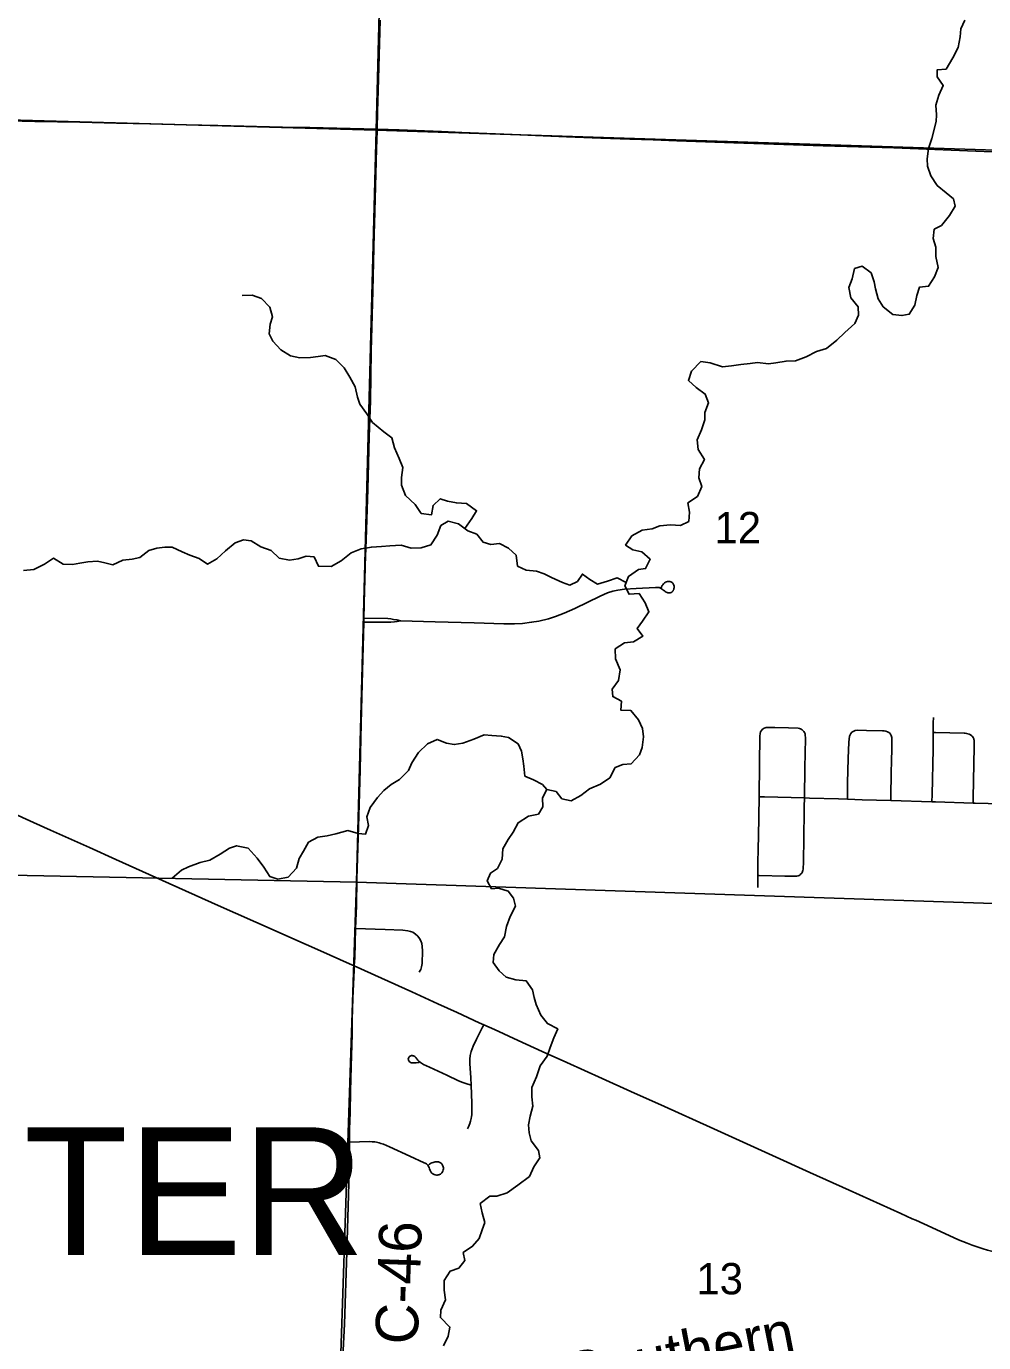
# Model space of a CAD drawing. Extents: x 0 to 34, y 0 to 22.
# Drawn here: x 4.336 to 5.615, y 17.97 to 19.729 of the extents above; entities that cross this region are included whole.
import ezdxf

# ---------------------------------------------------------------- set-up
doc = ezdxf.new("R2010")
doc.units = 0
for name, color, linetype in [('GM_X_Corporation', 7, 'Continuous'), ('GM_X_County_Road', 7, 'Continuous'), ('GM_X_County_Road_Text', 7, 'Continuous'), ('GM_X_Minor_River', 7, 'Continuous'), ('GM_X_Rail_Line_Text', 7, 'Continuous'), ('GM_X_Section_Text', 7, 'Continuous'), ('GM_X_State_Route', 7, 'Continuous'), ('GM_X_Township_Road', 7, 'Continuous'), ('GM_X_Township_Text', 7, 'Continuous')]:
    doc.layers.add(name, color=color, linetype=linetype)

msp = doc.modelspace()

# ---------------------------------------------------------------- linework, layer by layer
at = {"layer": 'GM_X_Corporation'}
for points in [[(3.7914, 20.5987), (3.8107, 20.5986), (4.8123, 20.5837), (4.829, 20.5833), (4.8036, 19.5906), (3.7742, 19.6197)], [(4.829, 20.5833), (5.8164, 20.5638), (5.7981, 19.5979), (5.7974, 19.5584), (4.8036, 19.5906)], [(3.7742, 19.6197), (4.8036, 19.5906), (4.7775, 18.5857), (3.7435, 18.6067)], [(4.8036, 19.5906), (5.7974, 19.5584), (5.7756, 18.586), (5.7749, 18.5522), (4.7775, 18.5857)], [(3.7435, 18.6067), (4.7775, 18.5857), (4.7439, 17.5807), (3.7219, 17.5988)], [(4.7775, 18.5857), (5.7749, 18.5522), (5.7585, 17.5867), (5.7581, 17.5537), (4.7439, 17.5807)]]:
    msp.add_lwpolyline(points, close=True, dxfattribs=at)
at = {"layer": 'GM_X_County_Road'}
for points in [[(4.8051, 19.5918), (4.8056, 19.6152), (4.8065, 19.6437), (4.8092, 19.7375)], [(4.8016, 19.4655), (4.8044, 19.5655), (4.8051, 19.5898), (4.8051, 19.5918)], [(4.7886, 18.9874), (4.7891, 19.0092), (4.7905, 19.0433), (4.7926, 19.111), (4.7936, 19.1452), (4.7946, 19.1809), (4.796, 19.2289), (4.7971, 19.2953), (4.7993, 19.3761), (4.8013, 19.4525), (4.8016, 19.4655)], [(4.7871, 18.9333), (4.7872, 18.9384), (4.7877, 18.9564), (4.7883, 18.9775), (4.7886, 18.9874)], [(4.7763, 18.5237), (4.7773, 18.5541), (4.778, 18.5901), (4.7796, 18.6453), (4.7804, 18.6745), (4.7823, 18.736), (4.7834, 18.7782), (4.7843, 18.8161), (4.7855, 18.8676), (4.7871, 18.9333)], [(5.548, 18.7858), (5.5482, 18.7985), (5.5483, 18.8059)], [(5.3153, 18.7), (5.316, 18.7437), (5.3164, 18.7809), (5.3169, 18.7844), (5.3175, 18.7866), (5.3185, 18.7884), (5.3196, 18.7898)], [(5.3759, 18.6984), (5.3767, 18.7392), (5.377, 18.7578), (5.3774, 18.7783), (5.3771, 18.7825), (5.3768, 18.7841), (5.3763, 18.7856), (5.3754, 18.7872), (5.3745, 18.7882), (5.3731, 18.7895), (5.3717, 18.7904), (5.3706, 18.7908), (5.3694, 18.7912), (5.3678, 18.7915), (5.3545, 18.792), (5.3364, 18.7926), (5.3248, 18.7925), (5.3236, 18.7922), (5.3221, 18.7915), (5.3207, 18.7907), (5.3196, 18.7898)], [(5.4335, 18.6966), (5.4336, 18.7009), (5.4337, 18.7187), (5.4345, 18.751), (5.4355, 18.7727), (5.4364, 18.7808), (5.437, 18.7828), (5.438, 18.7846), (5.4394, 18.7861), (5.4411, 18.7873), (5.4436, 18.7884), (5.4468, 18.7889), (5.4587, 18.7886), (5.4804, 18.7879), (5.4827, 18.7878), (5.4848, 18.7874), (5.4868, 18.7868), (5.488, 18.7863), (5.4895, 18.7852), (5.491, 18.7837), (5.4919, 18.7818), (5.4926, 18.7792), (5.4927, 18.7764), (5.4928, 18.7735), (5.4926, 18.7604), (5.4924, 18.7511), (5.4921, 18.7287), (5.4916, 18.7032), (5.4915, 18.7001), (5.4915, 18.6948)], [(5.5464, 18.6931), (5.5465, 18.7028), (5.5478, 18.7636), (5.548, 18.7858)], [(5.6014, 18.6915), (5.6016, 18.6985), (5.6024, 18.7437), (5.6027, 18.7666), (5.6026, 18.7753), (5.6025, 18.7764), (5.6023, 18.7774), (5.6019, 18.7783), (5.6014, 18.7792), (5.6006, 18.7802), (5.5997, 18.7813), (5.5979, 18.7826), (5.596, 18.7835), (5.5942, 18.7842), (5.5926, 18.7845), (5.5906, 18.7847), (5.5892, 18.7848), (5.5511, 18.7857), (5.548, 18.7858)], [(5.3138, 18.5947), (5.3138, 18.6107), (5.3142, 18.6312), (5.3144, 18.6467), (5.3153, 18.7)], [(5.3138, 18.5947), (5.3154, 18.5947), (5.3499, 18.594), (5.364, 18.5937), (5.366, 18.5939), (5.3676, 18.5943), (5.369, 18.5949), (5.3701, 18.5956), (5.3714, 18.5967), (5.3724, 18.5979), (5.373, 18.5988), (5.3735, 18.5999), (5.3739, 18.6014), (5.3742, 18.6031), (5.3743, 18.6054), (5.3746, 18.6106), (5.3746, 18.6187), (5.3751, 18.6392), (5.3757, 18.6864), (5.3759, 18.6984)], [(5.3153, 18.7), (5.3168, 18.7), (5.3225, 18.7), (5.3759, 18.6984)], [(5.3759, 18.6984), (5.3828, 18.6981), (5.4213, 18.6971), (5.4335, 18.6966)], [(5.4335, 18.6966), (5.453, 18.6959), (5.4915, 18.6948), (5.5464, 18.6931)], [(5.5464, 18.6931), (5.5512, 18.693), (5.6014, 18.6915)], [(5.6014, 18.6915), (5.604, 18.6914), (5.6563, 18.6898)], [(5.3136, 18.5785), (5.3137, 18.5847), (5.3137, 18.5884), (5.3138, 18.5947)], [(4.7745, 18.4739), (4.7752, 18.4853), (4.7763, 18.5237)], [(4.7683, 18.2384), (4.7681, 18.2557), (4.7688, 18.278), (4.7695, 18.3066), (4.7703, 18.3395), (4.7715, 18.3823), (4.7719, 18.4016), (4.7727, 18.4307), (4.7742, 18.468), (4.7745, 18.4739)], [(4.7501, 17.5815), (4.7502, 17.5833), (4.7508, 17.6033), (4.752, 17.6436), (4.754, 17.7038), (4.7551, 17.7448), (4.7551, 17.756), (4.7545, 17.7636), (4.7533, 17.7747), (4.7527, 17.7793), (4.752, 17.7872), (4.7514, 17.7918), (4.7525, 17.8123), (4.7544, 17.847), (4.7573, 17.909), (4.7597, 17.9604), (4.7614, 17.9952), (4.7647, 18.0914), (4.7676, 18.1989), (4.7683, 18.2384)], [(4.7683, 18.2384), (4.7949, 18.2393), (4.7986, 18.239), (4.8018, 18.2386), (4.8044, 18.2383), (4.8076, 18.2376), (4.8102, 18.2366), (4.8134, 18.2356), (4.8215, 18.2321), (4.8486, 18.2196), (4.868, 18.2109), (4.8694, 18.2101), (4.8708, 18.2093), (4.8717, 18.2086), (4.8727, 18.2075), (4.8739, 18.2058), (4.8745, 18.2044), (4.8752, 18.2026), (4.8759, 18.2007), (4.8769, 18.1989), (4.8781, 18.197), (4.8794, 18.196), (4.8814, 18.195), (4.8827, 18.1947), (4.8842, 18.1944), (4.8852, 18.1944), (4.8864, 18.1945), (4.8875, 18.1948), (4.8885, 18.1952), (4.8895, 18.1957), (4.8908, 18.1966), (4.8916, 18.1974), (4.8924, 18.1985), (4.893, 18.1998), (4.8935, 18.2015), (4.8937, 18.2029), (4.8936, 18.2042), (4.8934, 18.2056), (4.8926, 18.2077), (4.8913, 18.2095), (4.8905, 18.2102), (4.8896, 18.2108), (4.8881, 18.2115), (4.887, 18.2119), (4.8854, 18.2121), (4.8841, 18.2121), (4.8826, 18.2119), (4.8812, 18.2117), (4.8799, 18.2113), (4.8781, 18.2107), (4.8768, 18.2101), (4.8757, 18.2094), (4.875, 18.2088), (4.8735, 18.2076)]]:
    msp.add_lwpolyline(points, dxfattribs=at)
at = {"layer": 'GM_X_Minor_River'}
for points in [[(5.5519, 19.6023), (5.5524, 19.6111), (5.5516, 19.624), (5.5554, 19.6372), (5.5614, 19.6503), (5.5533, 19.6619), (5.5535, 19.6714), (5.5653, 19.6723), (5.5744, 19.6872), (5.5812, 19.7011), (5.5839, 19.7155), (5.5849, 19.7261), (5.5901, 19.7374)], [(5.2103, 19.0624), (5.2214, 19.0679), (5.2224, 19.08), (5.22, 19.0926), (5.233, 19.1011), (5.239, 19.1143), (5.2347, 19.1261), (5.236, 19.1379), (5.2423, 19.1506), (5.2339, 19.1637), (5.2326, 19.177), (5.2385, 19.1902), (5.243, 19.2034), (5.2428, 19.2132), (5.2476, 19.2261), (5.2433, 19.2379), (5.2313, 19.2469), (5.2209, 19.2562), (5.2253, 19.2686), (5.2377, 19.2813), (5.2501, 19.2799), (5.2667, 19.2746), (5.2785, 19.2759), (5.291, 19.2776), (5.3036, 19.2789), (5.3135, 19.2802), (5.3282, 19.2784), (5.3377, 19.2797), (5.3514, 19.2821), (5.364, 19.2826), (5.3781, 19.2877), (5.3919, 19.295), (5.4056, 19.2989), (5.4191, 19.31), (5.4299, 19.3204), (5.4434, 19.3323), (5.4482, 19.3432), (5.448, 19.3546), (5.438, 19.3666), (5.4352, 19.3803), (5.4396, 19.392), (5.4429, 19.4056), (5.4532, 19.4088), (5.4652, 19.3998), (5.4691, 19.388), (5.4708, 19.3785), (5.4744, 19.3651), (5.4814, 19.3547), (5.4941, 19.3443), (5.5062, 19.3429), (5.5161, 19.3446), (5.5235, 19.357), (5.526, 19.3698), (5.5297, 19.3808), (5.5418, 19.382), (5.55, 19.3948), (5.5548, 19.4072), (5.5517, 19.4217), (5.5516, 19.4342), (5.548, 19.4457), (5.5494, 19.4582), (5.5593, 19.4633), (5.5698, 19.4764), (5.5773, 19.4891), (5.5752, 19.4987), (5.5655, 19.5068), (5.5532, 19.5169), (5.5451, 19.5296), (5.5404, 19.5426), (5.5398, 19.5525), (5.5416, 19.5661), (5.5464, 19.5793), (5.5519, 19.6023)], [(4.9224, 19.0582), (4.9318, 19.0716), (4.938, 19.0821), (4.9246, 19.0919), (4.9109, 19.0925), (4.8992, 19.095), (4.8894, 19.0982), (4.8798, 19.0893), (4.8776, 19.0765), (4.864, 19.0786), (4.8559, 19.0905), (4.8429, 19.1026), (4.8378, 19.1163), (4.8376, 19.1266), (4.8394, 19.1398), (4.8343, 19.1521), (4.8282, 19.1662), (4.8246, 19.1796), (4.8138, 19.1874), (4.7989, 19.1998), (4.7911, 19.2114), (4.7819, 19.2244), (4.779, 19.234), (4.7759, 19.2477), (4.7685, 19.2604), (4.7608, 19.273), (4.7497, 19.2843), (4.7357, 19.2895), (4.7262, 19.2881), (4.716, 19.2868), (4.7019, 19.2863), (4.6891, 19.2889), (4.6763, 19.2971), (4.6656, 19.3087), (4.6608, 19.3186), (4.6622, 19.3315), (4.6651, 19.3413), (4.6615, 19.3539), (4.6507, 19.3659), (4.6379, 19.3703), (4.6247, 19.3698)], [(5.1376, 18.9863), (5.1259, 18.9923), (5.1129, 18.988), (5.0996, 18.9841), (5.0891, 18.99), (5.0794, 18.9974), (5.0727, 18.9877), (5.0624, 18.9826), (5.0526, 18.9862), (5.0379, 18.9929), (5.0282, 18.9976), (5.018, 19.0013), (5.004, 19.0027), (4.9927, 19.0082), (4.9907, 19.0227), (4.9807, 19.032), (4.9687, 19.0383), (4.9569, 19.037), (4.9467, 19.0402), (4.9382, 19.0506), (4.9261, 19.0554), (4.9138, 19.0648), (4.8998, 19.0681), (4.8902, 19.0622), (4.8854, 19.0494), (4.8769, 19.0366), (4.8639, 19.0327), (4.8506, 19.0322), (4.837, 19.0359), (4.8218, 19.0354), (4.8108, 19.0341), (4.7975, 19.0336), (4.7835, 19.0312), (4.7705, 19.0258), (4.757, 19.015), (4.7436, 19.0077), (4.7265, 19.008), (4.7207, 19.0203), (4.7101, 19.0216), (4.6994, 19.0177), (4.688, 19.016), (4.674, 19.0189), (4.6636, 19.029), (4.6496, 19.0338), (4.6369, 19.042), (4.6263, 19.043), (4.6152, 19.039), (4.6025, 19.0283), (4.5909, 19.0179), (4.5783, 19.0109), (4.5671, 19.0183), (4.5546, 19.0227), (4.5445, 19.0271), (4.5313, 19.0334), (4.5215, 19.0336), (4.5108, 19.0319), (4.5001, 19.0291), (4.4882, 19.0198), (4.4779, 19.0174), (4.4654, 19.0161), (4.452, 19.0099), (4.4414, 19.0124), (4.4312, 19.0149), (4.4187, 19.0136), (4.408, 19.0119), (4.3978, 19.0102), (4.3857, 19.0108), (4.3725, 19.0187), (4.3606, 19.0105), (4.3465, 19.0036), (4.3324, 19.0024)], [(4.9556, 18.166), (4.9651, 18.1662), (4.9788, 18.1708), (4.9931, 18.1808), (5.0085, 18.1923), (5.0144, 18.2054), (5.0226, 18.2174), (5.0205, 18.227), (5.0109, 18.24), (5.0081, 18.2507), (5.0071, 18.2617), (5.0096, 18.2731), (5.0133, 18.2863), (5.0116, 18.2989), (5.0119, 18.3114), (5.0182, 18.3257), (5.0227, 18.3404), (5.0324, 18.3531), (5.0364, 18.3648), (5.0412, 18.3776), (5.0464, 18.3897), (5.0325, 18.3968), (5.024, 18.4079), (5.0174, 18.4221), (5.015, 18.4316), (5.0125, 18.4419), (5.0044, 18.4538), (4.9904, 18.4553), (4.9776, 18.4589), (4.9679, 18.4675), (4.9601, 18.4786), (4.9611, 18.4892), (4.9686, 18.5024), (4.9752, 18.5129), (4.9777, 18.5265), (4.9829, 18.5397), (4.99, 18.5536), (4.9872, 18.5642), (4.9802, 18.5739), (4.9674, 18.5779), (4.9579, 18.577), (4.952, 18.5877), (4.9564, 18.5979), (4.966, 18.6041), (4.9723, 18.6165), (4.9729, 18.6302), (4.98, 18.6426), (4.9866, 18.6527), (4.9937, 18.6651), (5.0071, 18.6739), (5.0205, 18.6767), (5.0263, 18.6865), (5.0258, 18.6986), (5.0317, 18.7095), (5.0442, 18.707), (5.0519, 18.6973), (5.0644, 18.6945), (5.0774, 18.7014), (5.089, 18.7107), (5.1035, 18.7168), (5.1158, 18.725), (5.1233, 18.7389), (5.1332, 18.7428), (5.1446, 18.7441), (5.1555, 18.7557), (5.1594, 18.7659), (5.1609, 18.7799), (5.1596, 18.7909), (5.1541, 18.8028), (5.1441, 18.8151), (5.1308, 18.8154), (5.1314, 18.8275), (5.1198, 18.8338), (5.1189, 18.8437), (5.1274, 18.8553), (5.13, 18.8693), (5.1234, 18.8842), (5.1233, 18.8975), (5.1356, 18.9056), (5.1478, 18.9069), (5.16, 18.9143), (5.1527, 18.9246), (5.1597, 18.9344), (5.1683, 18.9471), (5.1632, 18.959), (5.1551, 18.9713), (5.1418, 18.9704), (5.1359, 18.9819), (5.1407, 18.9943), (5.1542, 19.0036), (5.1637, 19.0049), (5.17, 19.0173), (5.1588, 19.027), (5.1467, 19.0299), (5.137, 19.0362), (5.1452, 19.0485), (5.159, 19.0562), (5.1727, 19.0579), (5.1826, 19.0618), (5.197, 19.0631), (5.2103, 19.0624)], [(5.0317, 18.7095), (5.0258, 18.7161), (5.0141, 18.7224), (5.0025, 18.7275), (5.0012, 18.7408), (4.9999, 18.7507), (4.9978, 18.7606), (4.9934, 18.7706), (4.9807, 18.7792), (4.9709, 18.7809), (4.9584, 18.7819), (4.9482, 18.7825), (4.9344, 18.777), (4.9195, 18.7716), (4.9081, 18.7696), (4.8979, 18.7713), (4.8851, 18.7765), (4.8725, 18.7707), (4.8605, 18.7591), (4.8515, 18.7453), (4.8471, 18.7351), (4.8348, 18.7228), (4.824, 18.7162), (4.814, 18.7084), (4.8055, 18.6987), (4.7958, 18.6856), (4.7913, 18.6732), (4.7934, 18.6614), (4.7894, 18.6497), (4.7795, 18.651), (4.766, 18.6547), (4.7499, 18.6504), (4.7381, 18.6476), (4.726, 18.646), (4.7133, 18.639), (4.7067, 18.6274), (4.7008, 18.6176), (4.6971, 18.6044), (4.6863, 18.5925), (4.6722, 18.5897), (4.6616, 18.5933), (4.6535, 18.606), (4.6447, 18.6179), (4.6328, 18.6311), (4.6173, 18.6344), (4.6078, 18.6312), (4.5951, 18.6234), (4.5813, 18.615), (4.5687, 18.6122), (4.553, 18.6064), (4.5435, 18.6017), (4.5311, 18.5913)], [(4.8937, 17.966), (4.9001, 17.9792), (4.9022, 17.9913), (4.8895, 18.004), (4.8901, 18.0139), (4.8965, 18.0278), (4.8948, 18.0408), (4.8947, 18.0533), (4.9025, 18.066), (4.914, 18.07), (4.9221, 18.0801), (4.92, 18.0907), (4.9327, 18.0992), (4.9413, 18.1097), (4.9453, 18.121), (4.9489, 18.1308), (4.9453, 18.1438), (4.9429, 18.1563), (4.9556, 18.166)]]:
    msp.add_lwpolyline(points, dxfattribs=at)
at = {"layer": 'GM_X_State_Route'}
for points in [[(4.2899, 18.6909), (4.346, 18.6654), (4.3687, 18.6554), (4.4209, 18.632), (4.456, 18.6161), (4.4827, 18.6042), (4.5184, 18.5881), (4.5927, 18.5547), (4.666, 18.5221), (4.691, 18.5111), (4.7296, 18.4938), (4.7683, 18.4767), (4.7745, 18.4739)], [(4.7745, 18.4739), (4.8108, 18.4575), (4.8516, 18.4391), (4.8861, 18.4234), (4.912, 18.4115), (4.9415, 18.398), (4.9478, 18.3952), (4.9618, 18.3888), (4.9935, 18.3744), (5.0257, 18.3596), (5.0586, 18.3447), (5.1056, 18.3235), (5.1441, 18.3062), (5.1889, 18.2859), (5.25, 18.2582), (5.3333, 18.2206), (5.3831, 18.1979), (5.4359, 18.1742), (5.505, 18.143), (5.5201, 18.1361)], [(5.5201, 18.1361), (5.5248, 18.134), (5.5463, 18.1242), (5.5819, 18.1079), (5.5935, 18.1032), (5.6, 18.1008), (5.6081, 18.0979), (5.6148, 18.0957), (5.6207, 18.0941), (5.6279, 18.0922), (5.6346, 18.0907), (5.6493, 18.0879), (5.6637, 18.0859), (5.6753, 18.0849), (5.6921, 18.084), (5.7238, 18.0837), (5.7574, 18.0833), (5.7764, 18.0824)]]:
    msp.add_lwpolyline(points, dxfattribs=at)
at = {"layer": 'GM_X_Township_Road'}
for points in [[(3.7797, 19.6154), (3.7854, 19.6151), (3.8103, 19.6143), (3.8438, 19.6136), (3.8998, 19.6124), (3.952, 19.6114), (3.9986, 19.6101), (4.0663, 19.6088), (4.1676, 19.6064), (4.1962, 19.606), (4.3479, 19.6023), (4.4076, 19.6012), (4.4567, 19.5998), (4.5014, 19.5989), (4.5499, 19.5979), (4.5922, 19.597), (4.6785, 19.5948), (4.7152, 19.594), (4.8051, 19.5918)], [(4.8051, 19.5918), (4.8345, 19.5909), (4.891, 19.5887), (4.9184, 19.5877), (4.9855, 19.585), (5.0581, 19.5818), (5.1041, 19.5801), (5.1426, 19.5787), (5.1737, 19.5777), (5.2054, 19.5765), (5.2817, 19.5738), (5.3352, 19.5717), (5.401, 19.5697), (5.4955, 19.5668), (5.6048, 19.5625), (5.6615, 19.5604)], [(4.8364, 18.9349), (4.8825, 18.9338), (4.9347, 18.9324), (4.9745, 18.9311), (4.9887, 18.931), (4.9992, 18.9316), (5.0115, 18.933), (5.0212, 18.9347), (5.0339, 18.9377), (5.0433, 18.9406), (5.0549, 18.945), (5.069, 18.9514), (5.1031, 18.9681), (5.1129, 18.9722), (5.1201, 18.9746), (5.1268, 18.9761), (5.1355, 18.9773), (5.1511, 18.9783), (5.1772, 18.9795), (5.1801, 18.9794), (5.1811, 18.9794), (5.1818, 18.9793), (5.1827, 18.979), (5.1837, 18.9786), (5.185, 18.9779), (5.186, 18.9772), (5.1869, 18.9765), (5.1881, 18.9755), (5.1888, 18.9749), (5.1899, 18.9742), (5.1914, 18.9734), (5.1925, 18.973), (5.1935, 18.9726), (5.1947, 18.9725), (5.1958, 18.9724), (5.1968, 18.9726), (5.1978, 18.973), (5.1988, 18.9735), (5.1996, 18.9742), (5.2004, 18.975), (5.2008, 18.9758), (5.2014, 18.9769), (5.2017, 18.978), (5.2019, 18.9791), (5.202, 18.9802), (5.2019, 18.9814), (5.2016, 18.9825), (5.2012, 18.9835), (5.2008, 18.9844), (5.2, 18.9854), (5.1993, 18.986), (5.1984, 18.9868), (5.1975, 18.9872), (5.1963, 18.9875), (5.1953, 18.9877), (5.1941, 18.9877), (5.193, 18.9876), (5.1919, 18.9873), (5.1908, 18.9869), (5.1899, 18.9864), (5.1888, 18.9856), (5.1877, 18.9845), (5.1866, 18.9833), (5.1858, 18.9822), (5.1851, 18.9805), (5.1845, 18.979)], [(4.7871, 18.9333), (4.7999, 18.9333), (4.8203, 18.9333), (4.8234, 18.9334), (4.8281, 18.9336), (4.8317, 18.9339), (4.8364, 18.9349)], [(4.7872, 18.9384), (4.8193, 18.9379), (4.8234, 18.9375), (4.827, 18.9369), (4.8314, 18.9362), (4.8364, 18.9349)], [(4.7763, 18.5237), (4.816, 18.5225), (4.8396, 18.5217), (4.8459, 18.5209), (4.8496, 18.52), (4.8526, 18.5188), (4.8564, 18.5163), (4.8593, 18.5137), (4.8617, 18.5106), (4.8635, 18.5072), (4.8648, 18.5036), (4.8654, 18.4998), (4.8656, 18.4941), (4.8651, 18.4773), (4.8648, 18.4749), (4.8645, 18.4728), (4.8639, 18.4709), (4.8633, 18.4691), (4.8625, 18.4676), (4.8614, 18.4657)], [(4.9307, 18.3145), (4.9303, 18.3244), (4.9288, 18.3436), (4.9288, 18.3492), (4.9295, 18.3541), (4.9309, 18.3595), (4.9335, 18.3665), (4.9377, 18.3761), (4.9412, 18.3829), (4.946, 18.3919), (4.9478, 18.3952)], [(4.8612, 18.345), (4.8594, 18.3446), (4.857, 18.3444), (4.8546, 18.3442), (4.8532, 18.3442), (4.8519, 18.3442), (4.8508, 18.3444), (4.8498, 18.3448), (4.8491, 18.3452), (4.8483, 18.3458), (4.8477, 18.3464), (4.8473, 18.3472), (4.8469, 18.348), (4.8467, 18.3491), (4.8469, 18.3505), (4.8473, 18.3516), (4.8478, 18.3524), (4.8485, 18.353), (4.8493, 18.3534), (4.8501, 18.3538), (4.8509, 18.354), (4.852, 18.354), (4.8529, 18.3539), (4.8538, 18.3537), (4.8547, 18.3533), (4.8554, 18.3528), (4.856, 18.3522), (4.8567, 18.3515), (4.8574, 18.3508), (4.858, 18.3499), (4.8593, 18.348), (4.861, 18.3461), (4.8629, 18.3446), (4.8672, 18.3422), (4.875, 18.3384), (4.8981, 18.3278), (4.9139, 18.3205), (4.9196, 18.3183), (4.9248, 18.3163), (4.9293, 18.3149), (4.9307, 18.3145)], [(4.926, 18.256), (4.9273, 18.2588), (4.9281, 18.261), (4.929, 18.2634), (4.9297, 18.2664), (4.9307, 18.27), (4.9312, 18.2727), (4.9316, 18.275), (4.9317, 18.2776), (4.9318, 18.2798), (4.9318, 18.2846), (4.9318, 18.2904), (4.9307, 18.3145)]]:
    msp.add_lwpolyline(points, dxfattribs=at)

# ---------------------------------------------------------------- texts
at = {"layer": 'GM_X_County_Road_Text'}
msp.add_text('C-46', height=0.05682, rotation=87.944, dxfattribs=at).set_placement((4.8591, 17.9673))
at = {"layer": 'GM_X_Rail_Line_Text'}
msp.add_text('Norfolk Southern', height=0.056629, rotation=11.0655, dxfattribs=at).set_placement((4.8088, 17.8492))
at = {"layer": 'GM_X_Section_Text'}
for s, p in [('12', (5.2558, 19.0386)), ('13', (5.2316, 18.035))]:
    msp.add_text(s, height=0.04186, rotation=0, dxfattribs=at).set_placement(p)
at = {"layer": 'GM_X_Township_Text'}
msp.add_text('CENTER', height=0.17045, rotation=0, dxfattribs=at).set_placement((3.8518, 18.0877))

doc.saveas('drawing.dxf')
